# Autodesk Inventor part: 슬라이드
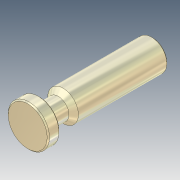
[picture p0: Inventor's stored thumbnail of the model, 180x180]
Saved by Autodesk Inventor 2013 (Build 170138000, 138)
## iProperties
Company: 한국ATC센터
Created: 2014-11
Part Number: 슬라이드
Document SubType Name: Modeling
Designer: KYOUNG IL JANG
Density: 7.86 g/cm^3
Material: 강, 연강
Mass: 436.103 g
Surface Area: 105.764 cm^2
Volume: 55.4838 cm^3
Author: KYOUNG IL JANG
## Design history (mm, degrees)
sketch "스케치1"
  geometry: L1 (19, 106.5)-(-19, 106.5) reference; L2 (0, 106.5)-(0, 212.5); L3 (0, 212.5)-(-13, 212.5); L4 (-13, 212.5)-(-13, 136.5); L5 (-9, 116.5)-(-17.5, 116.5); L6 (-17.5, 116.5)-(-17.5, 106.5); L7 (-17.5, 106.5)-(0, 106.5); L8 (-9, 116.5)-(-9, 132.5); L9 (-9, 132.5)-(-13, 136.5); 1 further point
  constraints: 18 end point, 3 perpendicular, 1 collinear, 1 horizontal, 1 midpoint, 1 parallel, 2 other
  dimensions: "d0" = 10 distance between parallel lines of L5 L7; "d1" = 35 diameter of L6 L2; "d2" = 106 distance of L2.start L2.end; "d3" = 135 deg angle of L9 L4; "d4" = 18 diameter of L8 L2; "d5" = 30 distance from line of L4.end L7; "d11" = 26 diameter of L4 L2
revolve "회전1" sketch "스케치1" stored, may be unused: angle "d6" = 90 deg
chamfer "모따기1" distance "d7" = 1; stored, may be unused: second distance "d8" = 2, angle "d9" = 45 deg
fillet "모깎기1" dims "d10" = 2
node "솔리드1"
